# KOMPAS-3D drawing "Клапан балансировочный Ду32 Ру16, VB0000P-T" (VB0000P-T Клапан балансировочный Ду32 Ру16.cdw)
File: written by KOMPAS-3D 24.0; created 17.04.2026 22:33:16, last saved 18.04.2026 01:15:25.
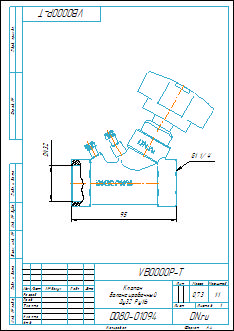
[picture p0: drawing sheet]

Document properties: Автор: tyuri; Форматы листов документа: A4; Полное имя файла: VB0000P-T Клапан балансировочный Ду32 Ру16.m3d; Масса: 0.73; Наименование: Клапан балансировочный Ду32 Ру16; Количество листов документа: 1; Примечание: D080-01094

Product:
- Body: Тело 2  | qty 1
    Масса: 1.39321
- Part/product: Клапан балансировочный Ду32 Ру16  | designation VB0000P-T
    Масса: 0.73
    Раздел спецификации: Прочие изделия
    Примечание: D080-01094

Views: Вид 1, Местный разрез 1, Справа
Referenced files in D:\Аутсорс\VB0000P-T Клапан балансировочный статический DN.ru\DN25\: VB0000P-T  Клапан балансировочный статический Ду25 Ру16.m3d
Referenced files in E:\Работа\Зайцев\АУТСОРС\Диман\Балансировка\VB0000P-T Клапан балансировочный DN.ru Ду15-50 Ру16\DN32\: VB0000P-T Клапан балансировочный Ду32 Ру16.m3d
Referenced files in D:\Аутсорс\VB0000P-T Клапан балансировочный статический DN.ru\DN20\: VB0000P-T  Клапан балансировочный статический Ду15 Ру16.cdw
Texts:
  VB0000P-T
  Клапан
  балансировочный
  Ду32 Ру16
  Клапан балансировочный Ду32 Ру16
  VB0000P-T Клапан балансировочный Ду32 Ру16
Dimensions and other numbers on the sheet: 0; 3; 2; 4; 32; 95; 1:1; 1; 0,73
